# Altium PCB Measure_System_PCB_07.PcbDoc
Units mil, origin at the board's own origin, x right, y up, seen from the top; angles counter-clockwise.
Board outline 5905.51 x 3943.07 mil, 2 copper layers (Top Layer, Bottom Layer); 44 components, 29 nets, 115 pads, 0 vias.
Unrouted connection lines stored in the file: 1.
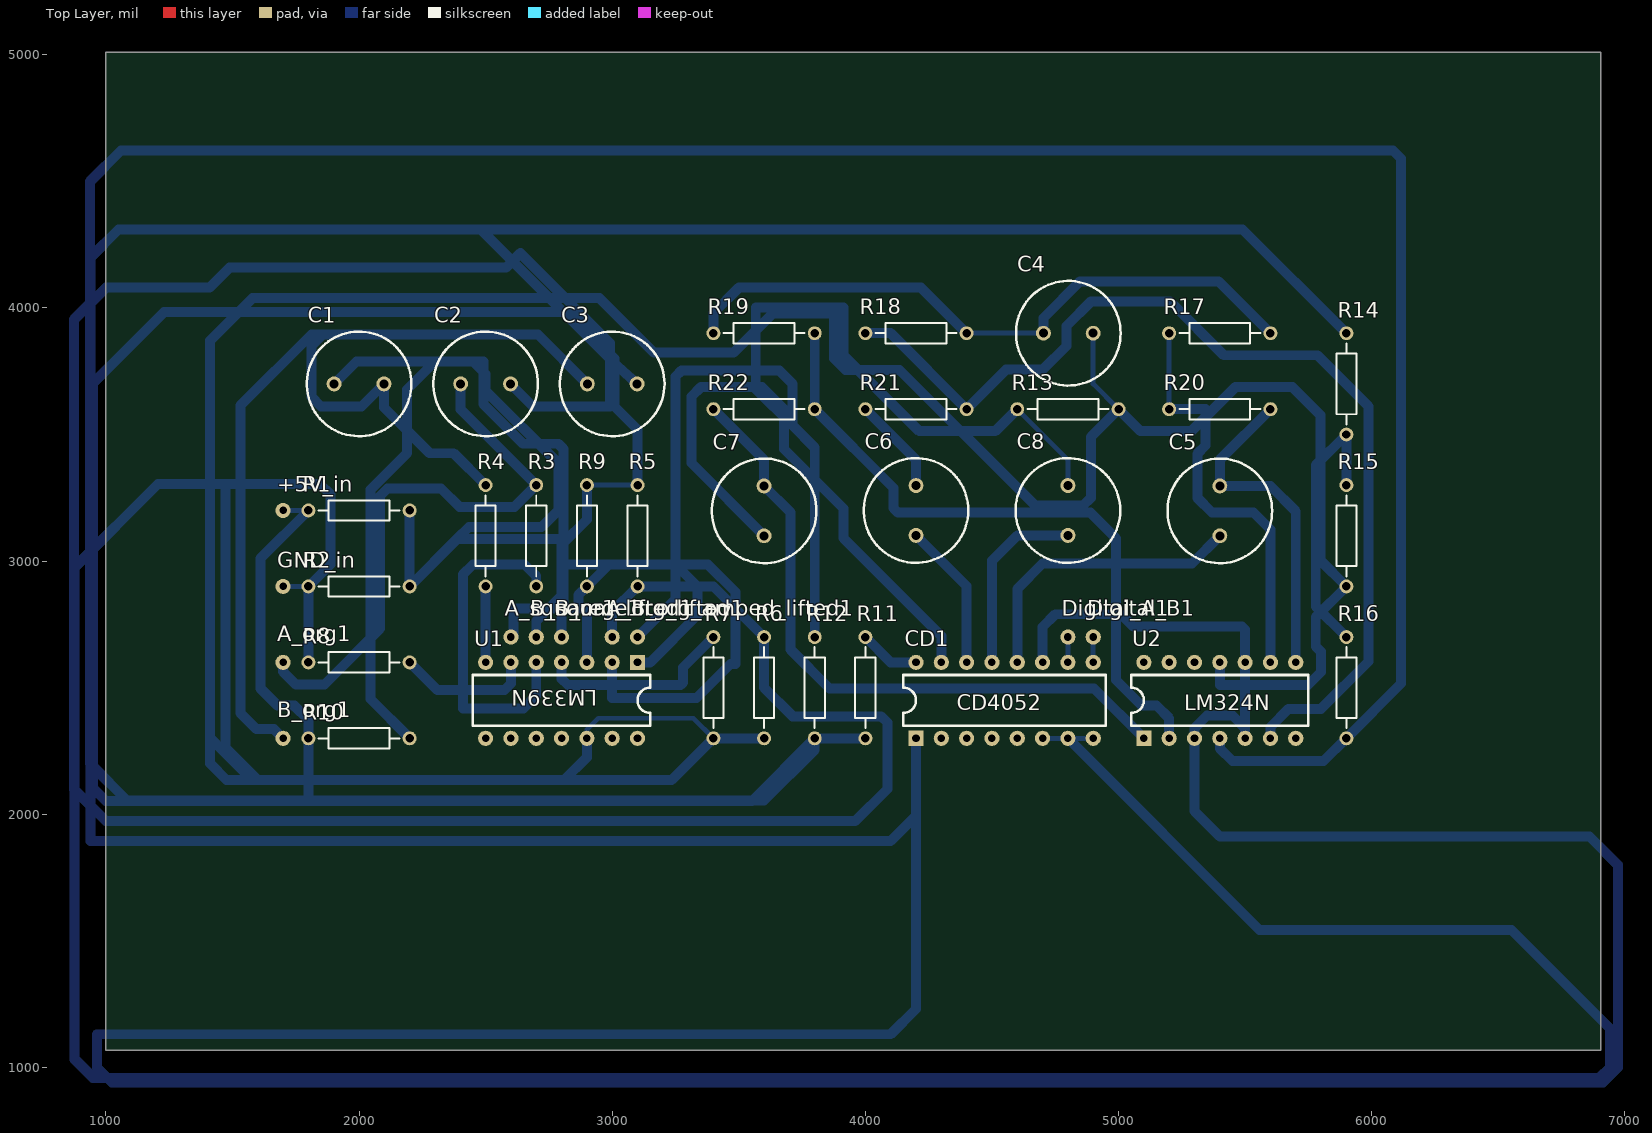
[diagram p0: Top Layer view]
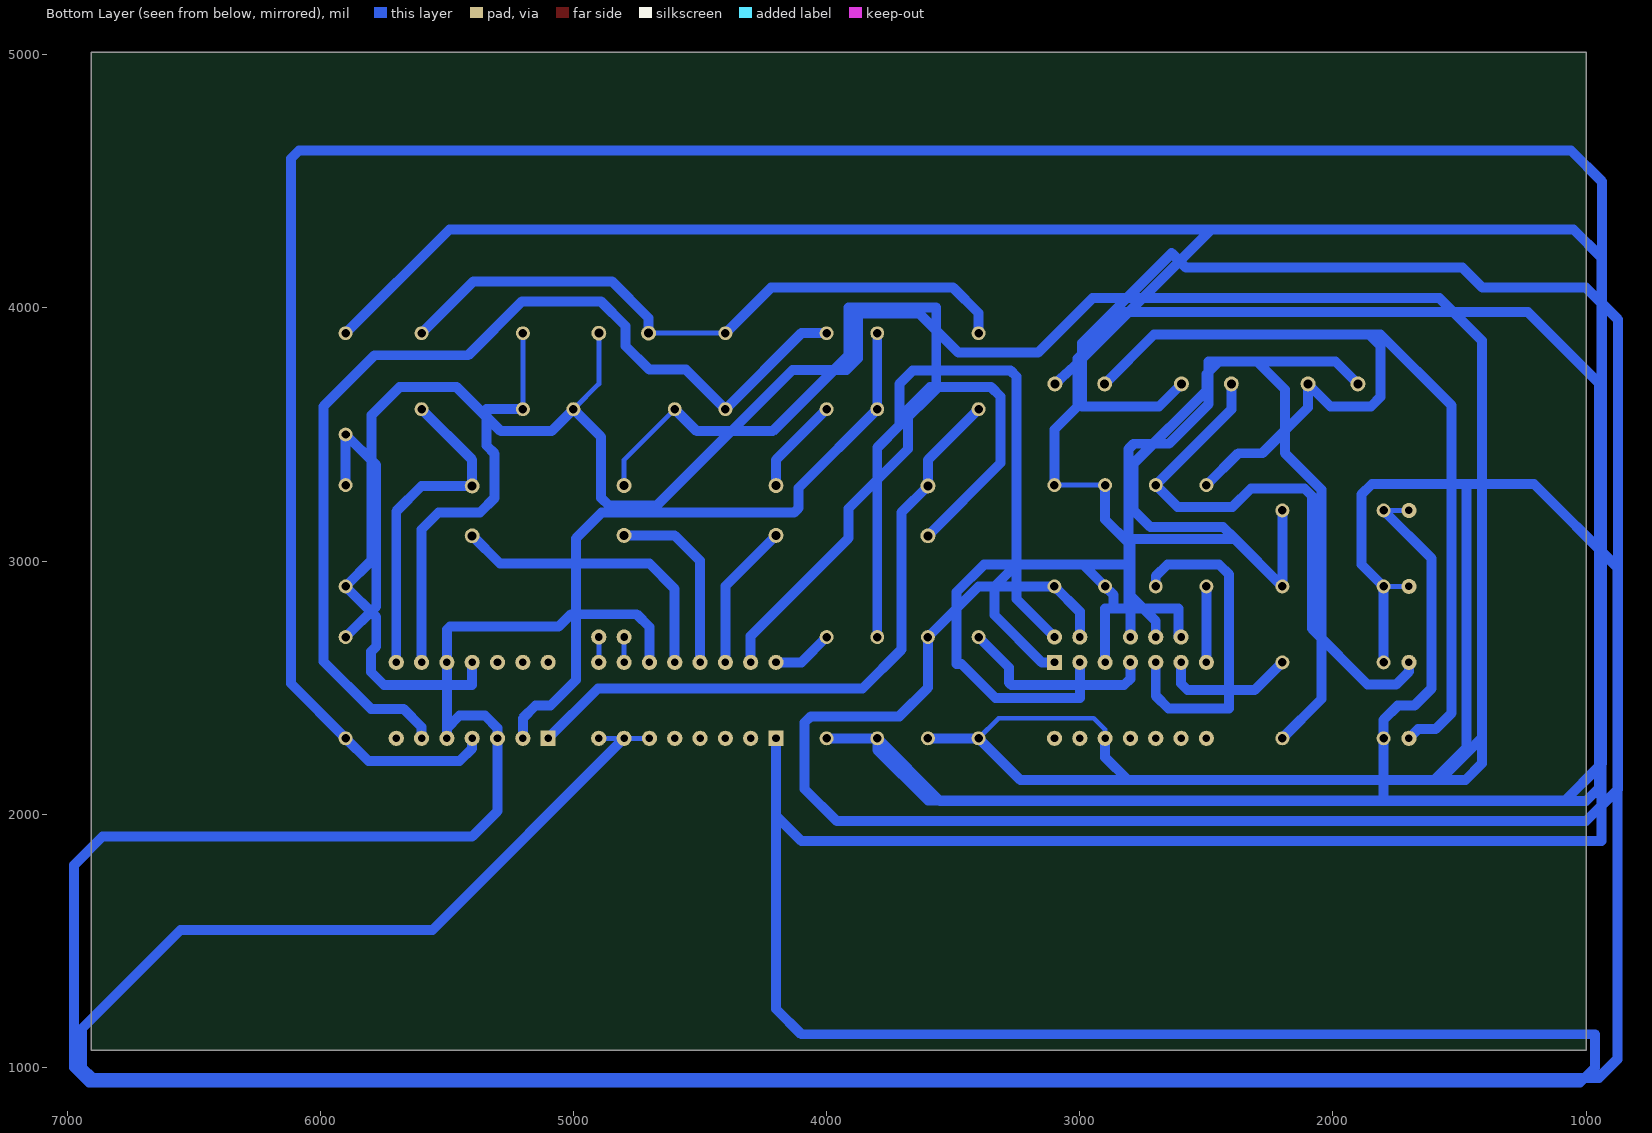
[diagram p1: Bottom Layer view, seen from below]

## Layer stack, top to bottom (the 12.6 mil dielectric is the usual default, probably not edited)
Top Solder: solder mask 0.4, Solder Resist, Dk 3.5
Top Layer: signal copper 1.4
Dielectric 1: dielectric 12.6, FR-4, Dk 4.8
Bottom Layer: signal copper 1.4
Bottom Solder: solder mask 0.4, Solder Resist, Dk 3.5

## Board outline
1000,1066.93 1000,5010 6905.51,5010 6905.51,1066.93

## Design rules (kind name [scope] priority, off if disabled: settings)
Clearance Clearance_1 [All] p1: gap=39.37 ignorepadtopadclearanceinfootprint=FALSE
PolygonConnect [All] p1: connectstyle=Relief reliefconductorwidth=10 reliefentries=4 polygonreliefangle="90 Angle" airgapwidth=10
RoutingLayers [All] p1: top layer_v5=FALSE bottom layer_v5=TRUE
RoutingVias [All] p1: holewidth=28 width=50 viastyle="Through Hole" minholewidth=28 minwidth=50 maxholewidth=28 maxwidth=50
SolderMaskExpansion [All] p1: expansion=4 istentingtop=FALSE
UnRoutedNet [All] p1: checkbadconnections=TRUE
Width [All] p1: maxlimit=393.7 minlimit=19.68 preferedwidth=39.37 minimp=50.000000 maximp=50.000000 favimp=50.000000
28 further rules are at their usual default settings.

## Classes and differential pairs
component class Part_Square: C1 C2 R1 R2 R3 R4 R5 R6 R7 R8 R9 R10 U1
component class Part_PGA: C3 C4 C5 C6 C7 C8 CD1 R11 R12 R13 R14 R15 R16 R17 R18 R19 R20 R21 R22 U2
component class Measure_System_Main: +5V_in A_org1 A_org_lifted1 A_square1 B_org1 B_org_amped_lifted1 B_org_lifted1 B_square1 Digital_A1 Digital_B1 GND_in

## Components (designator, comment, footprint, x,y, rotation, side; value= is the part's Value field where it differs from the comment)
+5V_in "Hole" Hole 1700,3200 r90 top
A_org1 "Hole" Hole 1700,2600 r90 top
A_org_lifted1 "Hole" Hole 3000,2700 r270 top
A_square1 "Hole" Hole 2600,2700 r270 top
B_org1 "Hole" Hole 1700,2300 r90 top
B_org_amped_lifted1 "Hole" Hole 3100,2700 r270 top
B_org_lifted1 "Hole" Hole 2800,2700 r180 top
B_square1 "Hole" Hole 2700,2700 r270 top
C1 "Cap Pol1" RB5-10.5 2000,3700 r180 top value=10u
C2 "Cap Pol1" RB5-10.5 2500,3700 r0 top value=10u
C3 "Cap Pol1" RB5-10.5 3000,3700 r0 top value=10u
C4 "Cap Pol1" RB5-10.5 4801.57,3900 r180 top value=10u
C5 "Cap Pol1" RB5-10.5 5400,3198.43 r270 top value=10u
C6 "Cap Pol1" RB5-10.5 4200,3200 r270 top value=10u
C7 "Cap Pol1" RB5-10.5 3600,3198.43 r270 top value=10u
C8 "Cap Pol1" RB5-10.5 4800,3200 r90 top value=10u
CD1 "CD4052" CD4052 4200,2300 r90 top
Digital_A1 "Hole" Hole 4800,2700 r270 top
Digital_B1 "Hole" Hole 4900,2700 r270 top
GND_in "Hole" Hole 1700,2900 r90 top
R1 "Res2" AXIAL-0.4 2000,3200 r180 top value=100k
R2 "Res2" AXIAL-0.4 2000,2900 r0 top value=100k
R3 "Res2" AXIAL-0.4 2700,3100 r90 top value=1k
R4 "Res2" AXIAL-0.4 2500,3100 r90 top value=1k
R5 "Res2" AXIAL-0.4 3100,3100 r90 top value=100k
R6 "Res2" AXIAL-0.4 3600,2500 r90 top value=100k
R7 "Res2" AXIAL-0.4 3400,2500 r90 top value=10k
R8 "Res2" AXIAL-0.4 2000,2600 r180 top value=10k
R9 "Res2" AXIAL-0.4 2900,3100 r270 top value=10k
R10 "Res2" AXIAL-0.4 2000,2300 r180 top value=10k
R11 "Res2" AXIAL-0.4 4000,2500 r270 top value=200
R12 "Res2" AXIAL-0.4 3800,2500 r270 top value=100k
R13 "Res2" AXIAL-0.4 4800,3600 r180 top value=100k
R14 "Res2" AXIAL-0.4 5900,3700 r90 top value=100k
R15 "Res2" AXIAL-0.4 5900,3100 r90 top value=100k
R16 "Res2" AXIAL-0.4 5900,2500 r90 top value=100k
R17 "Res2" AXIAL-0.4 5400,3900 r180 top value=50k
R18 "Res2" AXIAL-0.4 4200,3900 r180 top value=24k
R19 "Res2" AXIAL-0.4 3600,3900 r0 top value=12k
R20 "Res2" AXIAL-0.4 5400,3600 r0 top value=100k
R21 "Res2" AXIAL-0.4 4200,3600 r180 top value=100k
R22 "Res2" AXIAL-0.4 3600,3600 r180 top value=100k
U1 "LM339N" LM339N 3100,2600 r270 top
U2 "LM324N" LM324N 5100,2300 r90 top

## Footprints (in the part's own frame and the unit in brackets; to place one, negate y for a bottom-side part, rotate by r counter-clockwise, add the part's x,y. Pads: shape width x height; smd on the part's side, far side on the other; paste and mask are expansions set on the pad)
AXIAL-0.4 [mm] "Axial Device, Thru-Hole; 2 Leads; 0.4 in Pin Spacing"
  round 1.4 hole 0.85: 1(-5.08,0) 2(5.08,0)
  silkscreen extent -4.06,-1.02 4.06,1.02
CD4052 [mil]
  rect 60x60 hole 30: 1(0,0)
  round 60 hole 30 mask+4: 2(0,-100) 3(0,-200) 4(0,-300) 5(0,-400) 6(0,-500) 7(0,-600) 8(0,-700) 9(300,-700) 10(300,-600) 11(300,-500) 12(300,-400) 13(300,-300) 14(300,-200) 15(300,-100) 16(300,0)
  silkscreen extent 50,-750 250,50
Hole [mil]
  round 60 hole 30 mask+4: 1(0,0)
LM324N [mil]
  rect 60x60 hole 30: 1(0,0)
  round 60 hole 30 mask+4: 2(0,-100) 3(0,-200) 4(0,-300) 5(0,-400) 6(0,-500) 7(0,-600) 8(300,-600) 9(300,-500) 10(300,-400) 11(300,-300) 12(300,-200) 13(300,-100) 14(300,0)
  silkscreen extent 50,-650 250,50
LM339N [mil]
  rect 60x60 hole 30: 1(0,0)
  round 60 hole 30 mask+4: 2(0,-100) 3(0,-200) 4(0,-300) 5(0,-400) 6(0,-500) 7(0,-600) 8(300,-600) 9(300,-500) 10(300,-400) 11(300,-300) 12(300,-200) 13(300,-100) 14(300,0)
  silkscreen extent 50,-650 250,50
RB5-10.5 [mm] "Capacitor (Radial); 2 Leads"
  round 1.5 hole 0.9: 1(-2.5,0) 2(2.5,0)
  silkscreen extent -5.25,-5.25 5.25,5.25

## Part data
C1 C2 C3 C4 C5 C6 C7 C8: "Polarized Capacitor (Radial)"
R1 R2 R3 R4 R5 R6 R7 R8 R9 R10 R11 R12 R13 R14 R15 R16 R17 R18 R19 R20 R21 R22: "Resistor"

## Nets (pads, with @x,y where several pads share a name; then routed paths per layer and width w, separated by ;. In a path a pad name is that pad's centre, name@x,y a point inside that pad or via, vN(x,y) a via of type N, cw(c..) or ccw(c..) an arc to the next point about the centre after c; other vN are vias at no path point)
+5: +5V_in.1 R1.2 R5.2 R9.1 R10.2 R11.2 R12.2 R16.1 U1.3 U2.4 | length 23606.7
  Bottom Layer w19.68: +5V_in.1 R1.2 ; R9.1 R5.2
  Bottom Layer w39.37: R1.2 1610,3010 1610,2497.59 1678.85,2428.74 1744.26,2428.74 1800,2373 R10.2 1800,2054 ; U1.3 2900,2813 2807,2813 2807,3071 2900,3164 R9.1 ; R5.2 3100,3520 3009,3611 3009,3800 2826,3983 1230,3983 950,3703 950,2188 ; R11.2 R12.2 ; U2.4 5400,2260 5450,2210 5810,2210 R16.1 6116,2516 6116,4590 6084,4622 1060,4622 938,4500 938,2200 950,2188 ; 950,2188 950,2102 1000,2052 3552,2052 3554,2054 ; 950,2188 1084,2054 1800,2054 ; 1800,2054 3554,2054 ; 3554,2054 3600,2054 3800,2254 R12.2 ; 3554,2054 R12.2
B_org: B_org1.1 C1.1 C3.1 R4.2 | length 4218
  Bottom Layer w39.37: B_org1.1 1664,2336 1595,2336 1531,2400 1531,3614 1812,3895 1857.55,3895 ; R4.2 2374,3426 2279,3426 2098.43,3606.57 C1.1 2009.43,3611 1850,3611 1812,3649 1812,3849.45 1857.55,3895 ; C3.1 2706.57,3895 1857.55,3895
B_org_amp_1: C3.2 CD1.1 CD1.11 R14.2 U2.3 U2.5 U2.10 | length 26727.4
  Bottom Layer w39.37: C3.2 3022,3769 2481,4310 ; CD1.1 4200,1994 ; CD1.11 4700,2740 4750,2790 5010,2790 5059,2741 5488,2741 5500,2729 U2.10 5500,2340 ; U2.5 5500,2340 ; R14.2 5490,4310 2481,4310 ; 2481,4310 1050,4310 940,4200 940,1894 4100,1894 4200,1994 ; 4200,1994 4200,1231 4100,1131 965,1131 965,1000 1024,941 6913,941 6972,1000 6972,1800 6860,1912 5400,1912 5300,2012 U2.3 5300,2340 5350,2390 5450,2390 5500,2340
B_org_amp_2.5: C5.2 CD1.12 | length 1177
  Bottom Layer w39.37: CD1.12 4600,2890 4700,2990 5290,2990 C5.2
B_org_amp_5: C6.2 CD1.14 | length 584.4
  Bottom Layer w39.37: C6.2 4400,2901.57 CD1.14
B_org_amp_10: C7.2 CD1.15 | length 2343.5
  Bottom Layer w39.37: C7.2 3313,3387 3313,3650 3350,3687 3592,3687 3678,3601 3678,3443 3913.5,3207.5 3913.5,3090.5 4300,2704 CD1.15
B_org_amped: C8.1 CD1.13 | length 743
  Bottom Layer w39.37: CD1.13 4500,3001.57 4600,3101.57 C8.1
Digital_A: CD1.10 Digital_A1.1 | length 100
  Bottom Layer w19.68: CD1.10 Digital_A1.1
Digital_B: CD1.9 Digital_B1.1 | length 100
  Bottom Layer w19.68: CD1.9 Digital_B1.1
GND: C4.1 CD1.6 CD1.7 CD1.8 GND_in.1 R2.1 R6.1 R7.1 R8.2 R13.1 R15.1 U1.12 U2.11 | length 26634.4
  Bottom Layer w19.68: GND_in.1 1749,2900 R2.1 ; U1.12 2900,2334.21 2945,2379.21 3320.79,2379.21 R7.1 ; CD1.6 CD1.7 CD1.8 ; C4.1 4900,3700 R13.1
  Bottom Layer w39.37: R8.2 R2.1 1887,2987 1887,3250 1887,3264 1846,3305 1832,3305 1472,3305 ; U1.12 2900,2225 2810,2135 ; R6.1 R7.1 3235,2135 2810,2135 ; CD1.7 5557,1543 6552,1543 6941,1154 6941,1000 6900,959 950,959 877,1032 877,2976 1206,3305 1412,3305 ; U2.11 5400,2510 5748,2510 5800,2562 5800,2642 5779,2663 5779,2779 R15.1 5797,3003 5797,3577 5687,3687 5461,3687 5287,3513 5087,3513 R13.1 4891,3491 4891,3250 4860,3219 4671,3219 4135,3755 3922,3755 3877,3800 3877,3977 3633,3977 3479,3823 3165,3823 2949,4039 1580,4039 1412,3871 1412,3305 ; 1412,2300 1460.5,2251.5 1577,2135 ; 1412,2300 1412,3305 ; 1412,2300 1412,2200 1477,2135 1577,2135 ; 1412,3305 1472,3305 ; 1472,3305 1472,2263 1588.5,2146.5 1600,2135 ; 1577,2135 1600,2135 ; 1600,2135 2810,2135
NetA_org1_1: A_org1.1 C2.1 R3.2 | length 2275.4
  Bottom Layer w39.37: A_org1.1 1700,2563 1750,2513 1863.19,2513 2083,2732.81 2083,3257 2113,3287 2324,3287 2397.62,3213.38 2613.39,3213.38 R3.2 2401.57,3598.43 C2.1
NetA_org_lifted1_1: A_org_lifted1.1 C2.2 R5.1 R6.2 | length 10055
  Bottom Layer w39.37: C2.2 2687.42,3611 2991,3611 2991,3862 2637,4216 2580,4159 1488,4159 1409,4080 1000,4080 875,3955 875,2098 1000,1973 3960,1973 4087,2100 4087,2362 4062,2387 3713,2387 3600,2500 R6.2 3400,2900 R5.1 3000,2800 A_org_lifted1.1
NetA_square1_1: A_square1.1 R9.2 U1.2 | length 2116.1
  Bottom Layer w39.37: A_square1.1 2610,2700 2610,2813 2866,2813 2866,2866 R9.2 2987,2987 3377.57,2987 3487,2877.57 3487,2593.7 3467.7,2593.7 3333,2459 3000,2459 U1.2
NetB_org_amped_lifted1_1: B_org_amped_lifted1.1 C8.2 R12.1 R13.2 | length 4913.4
  Bottom Layer w19.68: R13.2 4800,3400 C8.2
  Bottom Layer w39.37: B_org_amped_lifted1.1 3250,2850 3250,3729 3273,3752 3567,3752 ; R12.1 3800,3200 3800,3448 3713,3535 ; R13.2 4513,3513 4213,3513 3913,3813 3913,4001 3567,4001 3567,3752 ; 3567,3752 3567,3681 3713,3535 ; 3567,3752 3661,3752 3713,3700 3713,3535
NetB_org_lifted1_1: B_org_lifted1.1 C1.2 R1.1 R2.2 | length 3117.2
  Bottom Layer w39.37: C1.2 1990.16,3788.58 2450.42,3788.58 2500,3739 2500,3673.15 2787,3386.15 2787,3200 2721.64,3134.64 2434.64,3134.64 2388,3088 ; R1.1 R2.2 2388,3088 ; B_org_lifted1.1 2800,3075 2787,3088 2388,3088
NetB_square1_1: B_square1.1 R10.1 U1.1 | length 4319.2
  Bottom Layer w39.37: R10.1 2045,2455 2045,3282 2189,3426 2189,3677.58 2300,3788.58 2491,3788.58 2491,3620.36 2647.85,3463.5 2787,3463.5 2807,3443.5 2807,2987 ; B_square1.1 2700,2763 2800,2863 ; U1.1 3150,2600 3337,2787 3337,2900 3250,2987 2807,2987 ; 2800,2863 2807,2870 2807,2987 ; 2800,2863 2800,2987 2807,2987
NetC4_2: C4.2 R17.1 R18.1 R19.1 | length 2601
  Bottom Layer w19.68: R18.1 C4.2
  Bottom Layer w39.37: R19.1 3400,3980 3500,4080 4220,4080 R18.1 ; C4.2 4703.15,3960.13 4847.98,4104.95 5395.05,4104.95 R17.1
NetC5_1: C5.1 R20.2 U2.8 | length 1324.3
  Bottom Layer w39.37: R20.2 5400,3400 C5.1 5600,3296.85 5700,3196.85 U2.8
NetC6_1: C6.1 R21.2 U2.7 | length 384.4
  Bottom Layer w39.37: R21.2 4200,3400 C6.1
NetC7_1: C7.1 R22.2 U2.1 | length 2616.3
  Bottom Layer w39.37: R22.2 3600,3400 C7.1 3705,3191.85 3705,2650 3858,2497 4903,2497 U2.1
NetCD1_16: CD1.16 R11.1 | length 241.4
  Bottom Layer w39.37: R11.1 4100,2600 CD1.16
NetR3_1: R3.1 U1.5 | length 1338.3
  Bottom Layer w39.37: U1.5 2700,2468 2650,2418 2410,2418 2410,2947 2450,2987 2654,2987 2700,2941 R3.1
NetR4_1: R4.1 U1.7 | length 300
  Bottom Layer w39.37: U1.7 R4.1
NetR7_2: R7.2 U1.4 | length 789.5
  Bottom Layer w39.37: U1.4 2800,2535 2825,2510 3270.57,2510 3280.02,2519.45 3280.02,2580.02 R7.2
NetR8_1: R8.1 U1.6 | length 539.5
  Bottom Layer w39.37: R8.1 2309,2491 2575,2491 2600,2516 U1.6
NetR14_1: R14.1 R15.2 R16.2 | length 1100.2
  Bottom Layer w39.37: R16.2 5779,2821 5779,3379 R14.1 R15.2
NetR17_2: R17.2 R20.1 U2.9 | length 1673.2
  Bottom Layer w19.68: R20.1 R17.2
  Bottom Layer w39.37: R20.1 5344,3600 5344,3457 5311,3424 5311,3250 5369,3192 5532.55,3192 5600,3124.55 U2.9
NetR18_2: R18.2 R21.1 U2.6 | length 4052.2
  Bottom Layer w39.37: R18.2 4100,3900 R21.1 4556,3756 4700,3756 4794,3850 4794,3928 4892,4026 5202.82,4026 5415.82,3813 5785.5,3813 5987,3611.5 5987,2603.43 5800,2416.43 5671.43,2416.43 5600,2345 U2.6
NetR19_2: R19.2 R22.1 U2.2 | length 2659.7
  Bottom Layer w39.37: R19.2 R22.1 4111,3289 4111,3209 4129,3191 4889,3191 4990,3090 4990,2530 5091,2429 5150,2429 5200,2379 U2.2
pads on no net: CD1.2 CD1.3 CD1.4 CD1.5 U1.8 U1.9 U1.10 U1.11 U1.13 U1.14 U2.12 U2.13 U2.14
